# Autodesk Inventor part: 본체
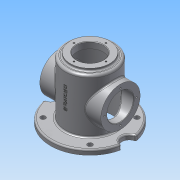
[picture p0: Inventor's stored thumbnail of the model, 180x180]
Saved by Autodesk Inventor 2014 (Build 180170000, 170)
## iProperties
Created: 2018-04
Part Number: 본체
Material: 알루미늄 6061
Document SubType Name: Modeling
Designer: 703
Density: 2.71 g/cm^3
Appearance: 알루미늄 - 평지
Mass: 1151.3 g
Surface Area: 1200.31 cm^2
Volume: 424.834 cm^3
Author: 703
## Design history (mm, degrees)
sketch "스케치1"
  geometry: C1 r 50 at (0, 0); 1 further point
  constraints: 1 centre point, 1 coincident
  dimensions: "d0" = 100 diameter of C1
extrude "돌출1" new body sketch "스케치1" distance "d1" = 110; taper "d2" = 0 deg
sketch "스케치2"
  geometry: C1 r 50 at (0, 0) reference; C2 r 80 at (0, 0)
  constraints: 1 centre point, 1 coincident
  dimensions: "d3" = 160 diameter of C2
extrude "돌출2" join sketch "스케치2" distance "d4" = 10; taper "d5" = 0 deg
sketch "스케치3"
  geometry: C1 r 80 at (0, 0) reference; C2 r 50 at (0, 0)
  constraints: 1 centre point, 1 coincident
  dimensions: "d6" = 100 diameter of C2
extrude "돌출3" join sketch "스케치3" distance "d7" = 8; taper "d8" = 0 deg
sketch "스케치4"
  geometry: C1 r 50 at (0, 0) reference; C2 r 45 at (0, 0)
  constraints: 1 centre point, 1 coincident
  dimensions: "d9" = 90 diameter of C2
extrude "돌출4" cut sketch "스케치4" distance "d10" = 120; taper "d11" = 0 deg
node "작업 평면1"
sketch "스케치6"
  geometry: L1 (-80, -10)-(80, -10) reference; C1 r 40 at (0, 50); 1 further point
  constraints: 1 centre point, 1 vertical alignment
  dimensions: "d13" = 60 distance from line of L1 C1.centre; "d14" = 80 diameter of C1
extrude "돌출5" join sketch "스케치6" stored distance "d15" = 120; taper "d16" = 0 deg
sketch "스케치7"
  geometry: C1 r 40 at (0, 0) reference; C2 r 27 at (0, 0); 1 further point
  constraints: 1 centre point, 1 coincident
  dimensions: "d17" = 54 diameter of C2
extrude "돌출6" cut sketch "스케치7" stored distance "d18" = 120; taper "d19" = 0 deg
node "작업 평면2"
sketch "스케치8"
  geometry: C1 r 40 at (0, 0); 1 further point
  constraints: 1 centre point, 1 coincident
  dimensions: "d21" = 80 diameter of C1
extrude "돌출7" join sketch "스케치8" stored distance "d22" = 120; taper "d23" = 0 deg
sketch "스케치9"
  geometry: C1 r 40 at (0, 0) reference; C2 r 27 at (0, 0)
  constraints: 1 centre point, 1 coincident
  dimensions: "d24" = 54 diameter of C2
extrude "돌출8" cut sketch "스케치9" stored distance "d25" = 120; taper "d26" = 0 deg
sketch "스케치10" dims "d27" = 65
  geometry: C1 r 27 at (0, 0) reference; C2 r 40 at (0, 0) reference; 3 further points
  constraints: 2 vertical alignment, 1 coincident, 2 other
hole "구멍1" sketch "스케치10" at (0, 32.5) diameter "d28" = 3.242; stored, may be unused: countersink angle "d32" = 90 deg, drill point angle "d34" = 118 deg; dims "d29" = 8, "d30" = 4, "d31" = 2, "d33" = 10
sketch "스케치11" dims "d38" = 65
  geometry: C1 r 27 at (0, 0) reference; C2 r 40 at (0, 0) reference; 2 further points
  constraints: 2 vertical alignment, 1 coincident, 2 other
hole "구멍2" sketch "스케치11" at (0, 32.5) diameter "d39" = 3.242; stored, may be unused: countersink angle "d43" = 90 deg, drill point angle "d45" = 118 deg; dims "d40" = 8, "d41" = 4, "d42" = 2, "d44" = 10
sketch "스케치12"
  geometry: C1 r 15 at (-80, 0); 1 further point
  constraints: 2 horizontal alignment, 1 centre point, 1 other
  dimensions: "d49" = 30 diameter of C1
extrude "돌출9" cut sketch "스케치12" stored distance "d50" = 10; taper "d51" = 0 deg
sketch "스케치13" dims "d53" = 135
  geometry: L1 (-56.569, 56.569)-(0, 0); L2 (0, 0)-(0, 80); C1 r 50 at (0, 0) reference; C2 r 5 at (-47.73, 47.73); A1 r 80 centre (0, 0) between (78.594, 14.934) and (-78.594, 14.934) reference; 1 further point
  constraints: 4 end point, 2 point on circle, 1 centre point, 1 coincident, 1 point on line, 3 other
  dimensions: "d52" = 45 deg angle of L2 L1; "d54" = 10 diameter of C2
extrude "돌출10" cut sketch "스케치13" stored distance "d55" = 10; taper "d56" = 0 deg
node "작업 평면3"
sketch "스케치14"
  geometry: L1 (78.594, -10)-(-78.594, -10) reference; L2 (-78.594, 0)-(78.594, 0) reference; 3 further points
  constraints: 1 midpoint, 1 vertical alignment, 1 other
  dimensions: "d60" = 70 distance from line of L1 point (0, 60)
feature "엠보싱1" sketch "스케치14" dims "d61" = 0.5, "d62" = 0
chamfer "모따기1" distance "d63" = 1; stored, may be unused: second distance "d64" = 2, angle "d65" = 45 deg
fillet "모깎기1" dims "d66" = 5
fillet "모깎기2" dims "d67" = 3
fillet "모깎기3" dims "d68" = 3
fillet "모깎기4" dims "d69" = 3
fillet "모깎기5" dims "d70" = 3
fillet "모깎기6" dims "d71" = 3
node "솔리드1"
mirror "대칭1"
pattern_circular "원형 패턴1" dims angle "d36" = 360 deg
mirror "대칭2"
pattern_circular "원형 패턴2" dims angle "d47" = 360 deg
mirror "대칭3"
pattern_circular "원형 패턴3" dims angle "d58" = 360 deg
other parameters: "d12" = 62, "d20" = -125
